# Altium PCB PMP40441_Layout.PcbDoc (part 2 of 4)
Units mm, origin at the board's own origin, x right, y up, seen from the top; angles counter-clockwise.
Board outline 66.04 x 61.04 mm, 4 copper layers (Top Layer, Layer 2, Layer 3, Bottom Layer), stack 2.028 mm thick; 208 components, 122 nets, 788 pads, 545 vias.
Unrouted connection lines stored in the file: 24.
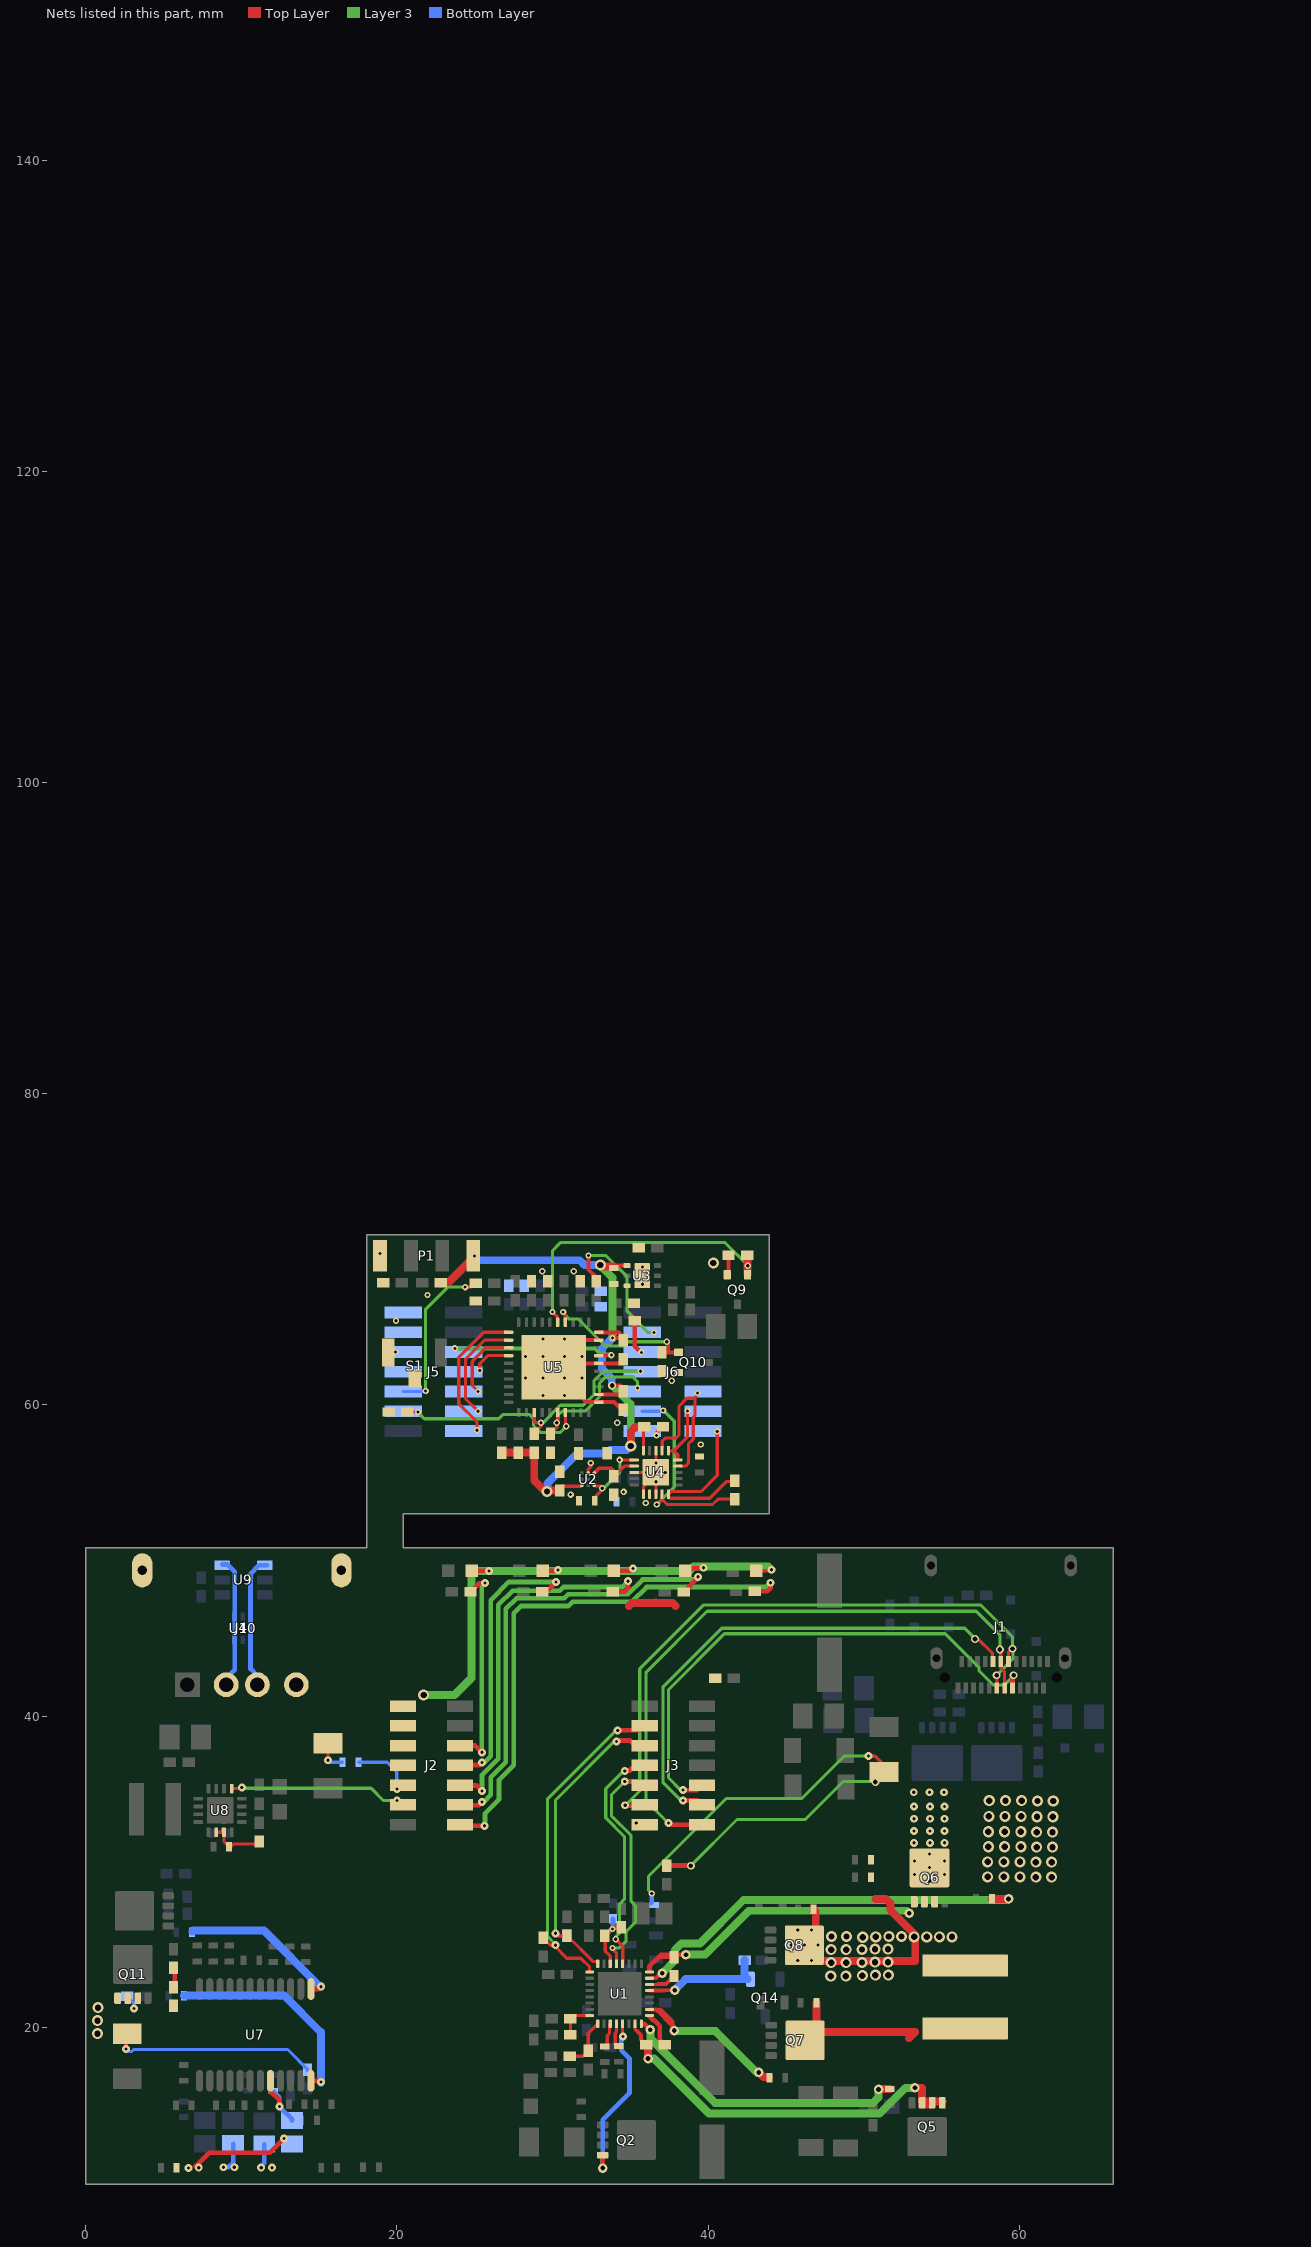
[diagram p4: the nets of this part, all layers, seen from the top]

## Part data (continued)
C115: "CAP, CERM, 1000 pF, 50 V, +/- 10%, X5R, 0402", Cap_Case=0402, Manufacturer=MuRata, Supplier Part Number 1=GRM155R61H102KA01D-ND, TempCo=X5R, Tolerance_%=10, Value1=Unknown, Value2=50V, ValueDisplayed=1000pF
C120 C136: "CAP, Polymer Hybrid, 56 µF, 25 V, +/- 20%, 50 ohm, 6.3x5.8 SMD", Manufacturer=Panasonic, Supplier Part Number 1=P15440CT-ND, Tolerance_%=20, Value1="50 ohm", Value2=25V, ValueDisplayed=56µF
C121 C122: "CAP, CERM, 47 µF, 25 V, +/- 20%, X5R, 1206_190", Cap_Case=1206, Manufacturer=TDK, Supplier Part Number 1=445-8047-1-ND, TempCo=X5R, Tolerance_%=20, Value1=Unknown, Value2=25V, ValueDisplayed=47µF
C125: "CAP, CERM, 1 µF, 25 V, +/- 10%, X5R, 0402", Cap_Case=0402, Manufacturer=MuRata, Supplier Part Number 1=490-10017-1-ND, TempCo=X5R, Tolerance_%=10, Value1=Unknown, Value2=25V, ValueDisplayed=1µF
C130 C131: "CAP, CERM, 330 pF, 50 V, +/- 5%, C0G/NP0, 0402", Cap_Case=0402, Manufacturer=MuRata, Supplier Part Number 1=490-1295-1-ND, TempCo=C0G/NP0, Tolerance_%=5, Value1=Unknown, Value2=50V, ValueDisplayed=330pF
C132 C135: "CAP, CERM, 22 µF, 35 V, +/- 20%, X5R, 1206_190", Cap_Case=1206, Manufacturer=TDK, Supplier Part Number 1=445-8045-1-ND, TempCo=X5R, Tolerance_%=20, Value1="0.002246 ohm", Value2=35V, ValueDisplayed=22µF
C137: "CAP, CERM, 1 µF, 16 V, +/- 10%, X5R, 0402", Cap_Case=0402, Manufacturer=TDK, Supplier Part Number 1=445-4978-1-ND, TempCo=X5R, Tolerance_%=10, Value1=Unknown, Value2=16V, ValueDisplayed=1µF
C140: "CAP, CERM, 33 pF, 50 V, +/- 5%, C0G/NP0, 0402", Cap_Case=0402, Manufacturer=MuRata, Supplier Part Number 1=81-GRM1555C1H330JA1D, TempCo=C0G/NP0, Tolerance_%=5, Value1=Unknown, Value2=50V, ValueDisplayed=33pF
C142: "CAP, CERM, 15 pF, 50 V, +/- 5%, C0G/NP0, 0402", Cap_Case=0402, Manufacturer=MuRata, Supplier Part Number 1=81-GRM1555C1H150JA1D, TempCo=C0G/NP0, Tolerance_%=5, Value1=Unknown, Value2=50V, ValueDisplayed=15pF
C143: "CAP, CERM, 1800 pF, 50 V, +/- 10%, X7R, 0402", Cap_Case=0402, Manufacturer=MuRata, Supplier Part Number 1=490-3246-1-ND, TempCo=X7R, Tolerance_%=10, Value1=Unknown, Value2=50V, ValueDisplayed=1800pF
C144: "CAP, CERM, 680 pF, 50 V, +/- 5%, C0G/NP0, 0402", Cap_Case=0402, Manufacturer=MuRata, Supplier Part Number 1=490-3240-1-ND, TempCo=C0G/NP0, Tolerance_%=5, Value1=Unknown, Value2=50V, ValueDisplayed=680pF
C151: "CAP, CERM, 2.2 µF, 16 V, +/- 10%, X5R, 0402", Cap_Case=0402, Manufacturer=TDK, Supplier Part Number 1=445-9085-1-ND, TempCo=X5R, Tolerance_%=10, Value1=Unknown, Value2=16V, ValueDisplayed=2.2µF
D1: "Diode, TVS, Uni, 24 V, 49 Vc, SOD-323", Manufacturer=Bourns, Supplier Part Number 1=CDSOD323-T24S-ND, Value1=W
D2 D3 D5: "Diode, Schottky, 45 V, 0.75 A, SOD-523", Manufacturer="Infineon Technologies", Supplier Part Number 1="BAS 52-02V H6327CT-ND", Value1=0.75A, Value2=0.6V
D4 D6: library part CMP-0005844-2, "Diode, Zener, 15 V, 300 mW, SOD-323", Manufacturer="NXP Semiconductor", Power_W=300mW, Supplier Part Number 1=568-6280-1-ND, Value1=0.3W
D7 D8: library part CMP-0082069-1, "Diode, Switching, 75 V, 0.15 A, SOD-323", Manufacturer="Micro Commercial Components", Supplier Part Number 1=1N4148WXTPMSCT-ND, Value1=0.15A, Value2=1V
D9: "Diode, Schottky, 30 V, 0.2 A, AEC-Q101, SOD-523", Manufacturer="ON Semiconductor", Supplier Part Number 1=RB521S30T1GOSCT-ND, Value1=0.2A, Value2=0.5V
D12 D13 D14 D15: "LED, Green, SMD", Color=green, Manufacturer=Lite-On, Power_TotalModule=0.1, Supplier Part Number 1=160-1183-1-ND, Value1=0.1W, Value2=2.1V
D16: "LED, Orange, SMD", Color=orange, Manufacturer=Lite-On, Power_TotalModule=0.075, Supplier Part Number 1=160-1434-1-ND, Value1=0.075W, Value2=2V
J1: "Receptacle, 0.5mm, USB TYPE C, R/A, SMT", Color=Black, Current_A=5, Manufacturer="Amphenol Canada", Supplier Part Number 1=12401610E4#2ACT-ND
J2 J3: "Receptacle, 1.27mm, 7x2, Gold, SMT", Manufacturer=Samtec, Supplier Part Number 1=SAM1226-07-ND
J4: "Connector, Receptacle, USB Type A, R/A, Bottom Mount TH", Manufacturer="Wurth Elektronik"
J5 J6: "Header, 1.27 mm, 7x2, Au, SMT", Manufacturer=FCI, Supplier Part Number 1=609-3730-ND
L5: "Inductor, Shielded, Composite, 2.2 µH, 3.7 A, 0.02 ohm, SMD", Manufacturer=Coilcraft, Supplier Part Number 1=994-XFL4020-222MEB, Value1="0.02 ohm", Value2=3.7A, ValueDisplayed=2.2µH
L8: "Inductor, Shielded, 2.2 µH, 16 A, 0.0067 ohm, AEC-Q200 Grade 1, SMD", Manufacturer=Coilcraft, Value1="0.0067 ohm", Value2=16A, ValueDisplayed=2.2µH
Logo5: library part Pb-Free
NT1: "Single point connection between nets."
P1: "Header, 2mm, 4x1, Gold, Black, R/A, SMT", Manufacturer=Harwin, Supplier Part Number 1=M22-5330405-ND
Q1 Q11: "MOSFET, N-CH, 25 V, 60 A, DQG0008A (VSON-CLIP-8)", Alternate Manufacturer=None, Manufacturer="Texas Instruments", Supplier Part Number 1=296-24522-1-ND, Value1="0.0044 ohm", Value2="6.2 nC"
Q2: "MOSFET, P-CH, -20 V, -60 A, VSON-CLIP-8", Alternate Manufacturer=None, Manufacturer="Texas Instruments", Value1="0.0065 ohm", Value2="10.8 nC"
Q3 Q4: library part CMP-0081533-1, "MOSFET, P-CH, -30 V, -35 A, PowerPAK 1212", Alternate Manufacturer=None, Manufacturer=Vishay-Siliconix, Supplier Part Number 1=SI7101DN-T1-GE3CT-ND, Value1="0.013 ohm", Value2="68 nC"
Q5 Q6 Q7 Q8: "MOSFET, N-CH, 30 V, 47 A, DQG0008A (VSON-CLIP-8)", Alternate Manufacturer=None, Manufacturer="Texas Instruments", Supplier Part Number 1=296-27210-1-ND, Value1="0.0094 ohm", Value2="3.9 nC"
Q9 Q10: "MOSFET, N-CH, 50 V, 0.21 A, SOT-323", Alternate Manufacturer=None, Manufacturer="Fairchild Semiconductor", Supplier Part Number 1=BSS138WCT-ND, Value1="6 ohm", Value2="1.1 nC"
Q14: library part CMP-0081321-1, "Transistor, NPN, 12 V, 2 A, SOT-23", Manufacturer="ON Semiconductor", Supplier Part Number 1=NSS12201LT1GOSCT-ND, Value1="2 A", Value2=330
R1 R2 R47 R53: "RES, 33, 5%, 0.125 W, 0805", Manufacturer=Vishay-Dale, Power_W=0.125, Supplier Part Number 1=541-33ACT-ND, TempCo="200 ppm/C", Tolerance_%=5, Value1=5%, Value2=0.125W, Value_Code=33R0, ValueDisplayed=33
R3 R6: "RES, 4.99, 1%, 0.063 W, 0402", Manufacturer=Vishay-Dale, Power_W=0.063, Supplier Part Number 1=541-4.99LLCT-ND, TempCo="100 ppm/C", Tolerance_%=1, Value1=1%, Value2=0.063W, Value_Code=4R99, ValueDisplayed=4.99
R4: "RES, 10 M, 5%, 0.063 W, 0402", Manufacturer=Vishay-Dale, Power_W=0.063, Supplier Part Number 1=541-10MJCT-ND, TempCo="200 ppm/C", Tolerance_%=5, Value1=5%, Value2=0.063W, Value_Code=10M0, ValueDisplayed=10M
R5: "RES, 3.0 M, 5%, 0.063 W, 0402", Manufacturer=Vishay-Dale, Power_W=0.063, Supplier Part Number 1=541-3.0MJCT-ND, TempCo="200 ppm/C", Tolerance_%=5, Value1=5%, Value2=0.063W, Value_Code=3M00, ValueDisplayed=3.0M
R7: "RES, 1.00 k, 1%, 0.125 W, 0805", Manufacturer=Vishay-Dale, Power_W=0.125, Supplier Part Number 1=541-1.00KCCT-ND, TempCo="100 ppm/C", Tolerance_%=1, Value1=1%, Value2=0.125W, Value_Code=1k00, ValueDisplayed=1.00k
R8: "RES, 1.0, 5%, 0.063 W, 0402", Manufacturer=Vishay-Dale, Power_W=0.063, Supplier Part Number 1=541-1.0JCT-ND, TempCo="200 ppm/C", Tolerance_%=5, Value1=5%, Value2=0.063W, Value_Code=1R00, ValueDisplayed=1.0
R9 R119: library part CMP-0026727-1, "RES, 1.00 M, 1%, 0.063 W, 0402", Manufacturer="Yageo America", Power_W=63mW, Supplier Part Number 1=311-1.00MLRCT-ND, TempCo="100 ppm/C", Tolerance_%=1%, Value2=0.063W, Value_Code=1M00, ValueDisplayed=1.00M
R10 R11 R12 R13 R16 R19 R34 R35 R76 R77 R81 R113: "RES, 0, 5%, 0.063 W, 0402", Manufacturer=Vishay-Dale, Power_W=0.063, Supplier Part Number 1=541-0.0JCT-ND, TempCo="200 ppm/C", Tolerance_%=5, Value1=5%, Value2=0.063W, Value_Code=0000, ValueDisplayed=0
R14 R32 R36 R87: "RES, 10.0 k, 1%, 0.063 W, 0402", Manufacturer=Vishay-Dale, Power_W=0.063, Supplier Part Number 1=541-10.0KLCT-ND, TempCo="100 ppm/C", Tolerance_%=1, Value1=1%, Value2=0.063W, Value_Code=10k0, ValueDisplayed=10.0k
R15: "RES, 470 k, 5%, 0.063 W, 0402", Manufacturer=Vishay-Dale, Power_W=0.063, Supplier Part Number 1=541-470KJCT-ND, TempCo="200 ppm/C", Tolerance_%=5, Value1=5%, Value2=0.063W, Value_Code=470k
R17: "RES, 196 k, 1%, 0.063 W, 0402", Manufacturer=Vishay-Dale, Power_W=0.063, Supplier Part Number 1=541-196KLCT-ND, TempCo="100 ppm/C", Tolerance_%=1, Value1=1%, Value2=0.063W, Value_Code=196k
R18: "RES, 1.0 M, 5%, 0.063 W, 0402", Manufacturer=Vishay-Dale, Power_W=0.063, Supplier Part Number 1=541-1.0MJCT-ND, TempCo="200 ppm/C", Tolerance_%=5, Value1=5%, Value2=0.063W, Value_Code=1M00, ValueDisplayed=1.0M
R20 R41 R42 R95: "RES, 100 k, 1%, 0.063 W, 0402", Manufacturer=Vishay-Dale, Power_W=0.063, Supplier Part Number 1=541-100KLCT-ND, TempCo="100 ppm/C", Tolerance_%=1, Value1=1%, Value2=0.063W, Value_Code=100k
R21: "RES, 200, 1%, 0.063 W, 0402", Manufacturer=Vishay-Dale, Power_W=0.063, Supplier Part Number 1=541-200LCT-ND, TempCo="100 ppm/C", Tolerance_%=1, Value1=1%, Value2=0.063W, Value_Code=200R, ValueDisplayed=200
R22 R122: library part CMP-0026815-1, "RES, 100 k, 0.1%, 0.063 W, 0402", Manufacturer="Susumu Co Ltd", Power_W=63mW, Supplier Part Number 1=RG10P100KBCT-ND, TempCo="25 ppm/C", Tolerance_%=0.1%, Value2=0.063W, Value_Code=100k
R23 R28 R128: "RES, 3.01 M, 1%, 0.063 W, 0402", Manufacturer=Vishay-Dale, Power_W=0.063, Supplier Part Number 1=541-3.01MLCT-ND, TempCo="100 ppm/C", Tolerance_%=1, Value1=1%, Value2=0.063W, Value_Code=3M01, ValueDisplayed=3.01M
R24: "RES, 2.00 M, 1%, 0.063 W, 0402", Manufacturer=Vishay-Dale, Power_W=0.063, Supplier Part Number 1=541-2.00MLCT-ND, TempCo="100 ppm/C", Tolerance_%=1, Value1=1%, Value2=0.063W, Value_Code=2M00, ValueDisplayed=2.00M
R25: library part CRCW0402100kJNED, "RES, 100 k, 5%, 0.063 W, 0402", Manufacturer=Vishay-Dale, Power_W=0.063, Supplier Part Number 1=541-100KJCT-ND, TempCo="200 ppm/C", Tolerance_%=5, Value1=5%, Value2=0.063W, Value_Code=100k
R26 R27: "RES, 100, 1%, 0.063 W, 0402", Manufacturer="Yageo America", Power_W=0.063, Supplier Part Number 1=311-100LRCT-ND, TempCo="100 ppm/C", Tolerance_%=1, Value1=1%, Value2=0.063W, Value_Code=100R, ValueDisplayed=100
R29: "RES, 1.00 M, 1%, 0.063 W, 0402", Manufacturer=Vishay-Dale, Power_W=0.063, Supplier Part Number 1=541-1.00MLCT-ND, TempCo="100 ppm/C", Tolerance_%=1, Value1=1%, Value2=0.063W, Value_Code=1M00, ValueDisplayed=1.00M
R30 R130: library part CMP-0026731-1, "RES, 330 k, 1%, 0.0625 W, 0402", Manufacturer="Yageo America", Power_W=62.5mW, Supplier Part Number 1=311-330KLRCT-ND, TempCo="100 ppm/C", Tolerance_%=1%, Value2=0.0625W, Value_Code=330k
R31: "RES, 200 k, 1%, 0.063 W, 0402", Manufacturer=Vishay-Dale, Power_W=0.063, Supplier Part Number 1=541-200KLCT-ND, TempCo="100 ppm/C", Tolerance_%=1, Value1=1%, Value2=0.063W, Value_Code=200k
R33: "RES, 220, 5%, 0.063 W, 0402", Manufacturer=Vishay-Dale, Power_W=0.063, Supplier Part Number 1=541-220JCT-ND, TempCo="200 ppm/C", Tolerance_%=5, Value1=5%, Value2=0.063W, Value_Code=220R, ValueDisplayed=220
R37: "RES, 100 k, 5%, 0.063 W, 0402", Manufacturer=Vishay-Dale, Power_W=0.063, Supplier Part Number 1=541-100KJCT-ND, TempCo="200 ppm/C", Tolerance_%=5, Value1=5%, Value2=0.063W, Value_Code=100k
R38: "RES, 47 k, 5%, 0.063 W, 0402", Manufacturer=Vishay-Dale, Power_W=0.063, Supplier Part Number 1=541-47KJCT-ND, TempCo="200 ppm/C", Tolerance_%=5, Value1=5%, Value2=0.063W, Value_Code=47k0, ValueDisplayed=47k
R45: "RES, 1.0 k, 5%, 0.063 W, 0402", Manufacturer=Vishay-Dale, Power_W=0.063, Supplier Part Number 1=541-1.0KJCT-ND, TempCo="200 ppm/C", Tolerance_%=5, Value1=5%, Value2=0.063W, Value_Code=1k00, ValueDisplayed=1.0k
R55 R57: "RES, 5.1 k, 5%, 0.063 W, 0402", Manufacturer=Vishay-Dale, Power_W=0.063, Supplier Part Number 1=541-5.1KJCT-ND, TempCo="200 ppm/C", Tolerance_%=5, Value1=5%, Value2=0.063W, Value_Code=5k10, ValueDisplayed=5.1k
R59: "Thermistor NTC, 10k ohm, 3%, 0402", Manufacturer=Panasonic, Power_W=0.066, Supplier Part Number 1=P12009CT-ND, Tolerance_%=3
R60 R72 R73: "RES, 0.01, 1%, 1 W, 1206", Manufacturer=Vishay-Dale, Power_W=1, Supplier Part Number 1=WSLP-.01CT-ND, TempCo="75 ppm/C", Value1=1%, Value2=1W, Value_Code=R010, ValueDisplayed=0.01
R62 R63: "RES, 100, 1%, 0.063 W, 0402", Manufacturer=Vishay-Dale, Power_W=0.063, Supplier Part Number 1=541-100LCT-ND, TempCo="100 ppm/C", Tolerance_%=1, Value1=1%, Value2=0.063W, Value_Code=100R, ValueDisplayed=100
R78 R79 R84: "RES, 10, 5%, 0.063 W, 0402", Manufacturer=Vishay-Dale, Power_W=0.063, Supplier Part Number 1=541-10JCT-ND, TempCo="200 ppm/C", Tolerance_%=5, Value1=5%, Value2=0.063W, Value_Code=10R0, ValueDisplayed=10
R82 R83: "RES, 56, 5%, 0.1 W, 0603", Manufacturer=Vishay-Dale, Power_W=0.1, Supplier Part Number 1=541-56GCT-ND, TempCo="200 ppm/C", Tolerance_%=5, Value1=5%, Value2=0.1W, Value_Code=56R0, ValueDisplayed=56
R86: "RES, 40.2 k, 1%, 0.063 W, 0402", Manufacturer=Vishay-Dale, Power_W=0.063, Supplier Part Number 1=541-40.2KLCT-ND, TempCo="100 ppm/C", Tolerance_%=1, Value1=1%, Value2=0.063W, Value_Code=40k2, ValueDisplayed=40.2k
R92: "RES, 383 k, 1%, 0.063 W, 0402", Manufacturer=Vishay-Dale, Power_W=0.063, Supplier Part Number 1=541-383KLCT-ND, TempCo="100 ppm/C", Tolerance_%=1, Value1=1%, Value2=0.063W, Value_Code=383k
R93: "RES, 80.6 k, 1%, 0.063 W, 0402", Manufacturer=Vishay-Dale, Power_W=0.063, Supplier Part Number 1=541-80.6KLCT-ND, TempCo="100 ppm/C", Tolerance_%=1, Value1=1%, Value2=0.063W, Value_Code=80k6, ValueDisplayed=80.6k
R94: "RES, 221 k, 1%, 0.063 W, 0402", Manufacturer=Vishay-Dale, Power_W=0.063, Supplier Part Number 1=541-221KLCT-ND, TempCo="100 ppm/C", Tolerance_%=1, Value1=1%, Value2=0.063W, Value_Code=221k
R98: "RES, 137 k, 1%, 0.063 W, 0402", Manufacturer=Vishay-Dale, Power_W=0.063, Supplier Part Number 1=541-137KLCT-ND, TempCo="100 ppm/C", Tolerance_%=1, Value1=1%, Value2=0.063W, Value_Code=137k
R99: "RES, 30.1 k, 1%, 0.063 W, 0402", Manufacturer=Vishay-Dale, Power_W=0.063, Supplier Part Number 1=541-30.1KLCT-ND, TempCo="100 ppm/C", Tolerance_%=1, Value1=1%, Value2=0.063W, Value_Code=30k1, ValueDisplayed=30.1k
R100 R101 R102 R103 R104: "RES, 3.3 k, 5%, 0.063 W, 0402", Manufacturer=Vishay-Dale, Power_W=0.063, Supplier Part Number 1=541-3.3KJCT-ND, TempCo="200 ppm/C", Tolerance_%=5, Value1=5%, Value2=0.063W, Value_Code=3k30, ValueDisplayed=3.3k
R105: "RES, 665 k, 1%, 0.063 W, 0402", Manufacturer=Vishay-Dale, Power_W=0.063, Supplier Part Number 1=541-665KLCT-ND, TempCo="100 ppm/C", Tolerance_%=1, Value1=1%, Value2=0.063W, Value_Code=665k
R106: "RES, 130 k, 1%, 0.063 W, 0402", Manufacturer=Vishay-Dale, Power_W=0.063, Supplier Part Number 1=541-130KLCT-ND, TempCo="100 ppm/C", Tolerance_%=1, Value1=1%, Value2=0.063W, Value_Code=130k
R112: "RES, 0.05, 1%, 1 W, 1206", Manufacturer=Panasonic, Power_W=1, Supplier Part Number 1=P0.05BVCT-ND, TempCo="50 ppm/C", Value1=1%, Value2=1W, Value_Code=R050, ValueDisplayed=0.05
S1: "Switch, SPST-NO, Off-Mom, 12 V, SMD", CurrentRating_mA=50, Manufacturer="Omron Electronic Components", Supplier Part Number 1=SW1021CT-ND
U1: library part CMP-0079371-1, "I2C Narrow VDC Buck-Boost Battery Charge Controller With System Power Monitor and Processor Hot Monitor, RSN0032B (WQFN-32)", Alternate Manufacturer="Texas Instruments", Alternate PartNumber=BQ25713RSNT
U2: library part CMP-0081747-1, "USB PD TCPCi Port Controller, YFP0009-C01 (DSBGA-9)", Alternate Manufacturer="Texas Instruments", Alternate PartNumber=TUSB422IYFPT, Operating Temprature Range="-40 to 85 C", Rating=Catalog
U3: "150-mA, 30-V, Ultra-Low IQ, Wide Input Low-Dropout Regulator with Reverse Current Protection, DRV0006A (WSON-6)", Alternate Manufacturer="Texas Instruments", Alternate PartNumber=TPS70933DRVT
U4: "USB Type C Interface Protector: Short-to-VBUS Over Voltage and IEC 61000-4-2 ESD Protection, RUK0020B", Alternate Manufacturer="Texas Instruments"
U5: "MSP430FR5949 16 MHz Ultra-Low-Power Microcontroller featuring 64 KB FRAM, 2 KB SRAM, 33 IO, RHA0040B (VQFN-40)", Alternate Manufacturer="Texas Instruments", Alternate PartNumber=MSP430FR5949IRHAT
U7: library part CMP-0077526-4, "3-5S Ultra Low-Power Voltage, Current, Temperature, and Open Wire Stackable Lithium-ion Battery Protector with Smart Cell Balancing, PW0024A (TSSOP-24)", Alternate Manufacturer="Texas Instruments"
U8: "4-17V 3A Step-Down Converter with DCS-Control, RGT0016C", Alternate Manufacturer="Texas Instruments", Alternate PartNumber=TLV62130RGTT
U9: "USB Dedicated Charging Port Controller, DBV0006A", Alternate Manufacturer="Texas Instruments", Alternate PartNumber=TPS2514ADBVT
U10: "DUAL CHANNEL HIGH SPEED ESD PROTECTION DEVICE, DRL0006A", Alternate Manufacturer="Texas Instruments"
ZZ1 ZZ5: library part AssemblyNoteLabel
ZZ2 ZZ3 ZZ4 ZZ6 ZZ7 ZZ8: library part AssemblyNote

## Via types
v1: diameter 0.711, hole 0.406, Top Layer to Bottom Layer, 205 vias
v2: diameter 0.508, hole 0.203, Top Layer to Bottom Layer, 152 vias
v3: diameter 0.406, hole 0.203, Top Layer to Bottom Layer, 67 vias
v4: diameter 0.5, hole 0.2, Top Layer to Bottom Layer, 66 vias
v5: diameter 0.508, hole 0.305, Top Layer to Bottom Layer, 16 vias
v6: diameter 0.61, hole 0.305, Top Layer to Bottom Layer, 16 vias
v7: diameter 0.403, hole 0.203, Top Layer to Bottom Layer, 9 vias
v8: diameter 0.5, hole 0.2, Top Layer to Bottom Layer, tented both sides, 6 vias
v9: diameter 0.5, hole 0.2, Top Layer to Bottom Layer, tented top, 5 vias
v10: diameter 0.914, hole 0.711, Top Layer to Bottom Layer, 2 vias
v11: diameter 0.229, hole 0.152, Top Layer to Bottom Layer, 1 vias

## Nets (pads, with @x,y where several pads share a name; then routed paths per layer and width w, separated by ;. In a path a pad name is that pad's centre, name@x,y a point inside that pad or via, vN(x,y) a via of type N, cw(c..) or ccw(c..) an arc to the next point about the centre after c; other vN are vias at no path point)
3V3: C7.2 C20.1 C22.2 C25.2 C26.2 P1.1 R25.2 R29.1 R31.1 R32.1 R36.1 R38.2 U2.A3 U3.1 U4.10 U5.32 U5.40 | length 48.6
  Top Layer w0.203: C7.2@30.48,54.762 31.833,54.762 U2.A3@31.89,54.82 ; C22.2@35.839,58.572 35.839,57.774 35.838,57.772 35.838,57.393 35.845,57.386 U4.10@35.845,57.059
  Top Layer w0.254: U5.32@32.978,60.662 34.373,60.662 C26.2@34.569,60.858 ; U5.40@32.978,64.662 34.245,64.662 ; v5(33.833,61.239) 34.366,61.239 34.544,61.062 C26.2@34.544,60.874 ; v3(33.858,64.287) C25.2@34.442,64.287 ; C20.1@33.975,68.951 U3.1@34.798,68.951 ; 34.29,64.643 34.544,64.389 C25.2@34.544,64.186 ; C25.2@34.544,64.141 C25.2@34.544,64.186 ; C25.2@34.62,64.16 C25.2@34.595,64.135 ; C25.2@34.773,64.135 C25.2@34.595,64.135 ; C25.2@34.544,64.186 C25.2@34.595,64.135
  Top Layer w0.508: R38.2@22.809,67.793 22.911,67.894 23.343,67.894 P1.1@25.006,69.558 ; R31.1@26.746,56.931 R29.1@28.794,56.931 ; R29.1@28.829,56.931 28.829,55.143 v1@29.616,54.356 ; v1@29.718,54.432 29.778,54.493 C7.2@30.455,54.493 ; v1@33.198,68.885 C20.1@33.934,68.885 ; v1(35.027,57.353) 35.027,58.268 35.331,58.572 C22.2@35.839,58.572
  Layer 3 w0.508: v1@33.071,68.961 33.858,68.174 v3(33.858,64.287) ; v5(33.833,61.239) 35.027,60.046 v1(35.027,57.353)
  Bottom Layer w0.254: R36.1@33.496,56.89 R36.1@33.528,56.89
  Bottom Layer w0.508: v3(24.994,69.571) 25.273,69.291 31.751,69.291 32.056,68.986 v1(33.071,68.986) ; v1@29.667,54.407 29.667,54.94 31.598,56.871 33.477,56.871 33.496,56.89 33.706,57.099 34.773,57.099 v1(35.027,57.353) ; v5@33.807,61.239 33.807,61.697 33.172,62.332 33.172,63.602 v3(33.858,64.287)
  other v1: 29.642,54.432
A_D+: J4.3 U9.1 U10.3 U10.4 | length 8.7
  Bottom Layer w0.305: 10.566,43.053 10.592,43.028 ; J4.3@11.074,41.986 11.024,42.037 11.024,42.596 10.592,43.028 ; U9.1@11.659,49.682 11.125,49.682 10.592,49.149 10.592,43.028
A_D-: J4.2 U9.6 U10.1 U10.6 | length 8.9
  Bottom Layer w0.305: U9.6@8.788,49.733 9.119,49.733 9.584,49.268 U10.1@9.584,46.394 ; J4.2@9.017,41.935 J4.2@9.071,41.989 ; J4.2@9.017,41.986 9.017,42.393 J4.2@9.024,42.399 ; J4.2@9.024,42.037 J4.2@9.024,42.399 ; U10.6@9.576,44.894 U10.1@9.576,46.394 ; U10.6@9.584,44.894 9.584,42.959 J4.2@9.024,42.399
AGND: C7.1 C16.2 C18.1 C19.1 C20.2 C21.1 C22.1 C23.2 C24.2 C25.1 C26.1 C27.2 C28.1 C29.2 C30.2 C31.2 C32.2 C33.1 C108.1 D12.2 D13.2 D14.2 D15.2 D16.2 J2.7 J2.9 J2.11 J2.13 J3.14 J5.7 J5.9 J5.11 J5.13 J6.14 P1.4 Q9.2 Q10.2 R19.2 R20.2 R23.2 R30.1 R37.1 R41.1 R42.1 R130.1 S1.2 S1.3 U2.C2 U3.3 U3.7@35.773,68.301 U4.8 U4.13 U4.16 U4.17 U4.18 U4.21@36.645,55.659 U5.31 U5.36 U5.39 U5.41@30.078,62.412 | length 53.1
  Top Layer w0.203: U2.C2@32.29,55.62 32.29,55.849 32.461,56.021 v3(32.461,56.261) ; U4.13@35.245,55.659 U4.21@36.035,55.659 ; U4.16@35.845,54.259 35.845,54.742 U4.21@35.966,54.864 ; U4.18@36.645,54.259 v4(36.645,55.059) U4.21@36.645,55.161 ; U4.8@36.645,57.059 v4(36.645,56.259) 36.645,56.218 U4.21@36.652,56.21 ; D16.2@43.092,49.34 44.005,49.34 v2(44.069,49.403)
  Top Layer w0.254: U5.41@31.242,62.662 U5.36@32.978,62.662 ; U5.41@31.269,64.162 U5.39@32.978,64.162 ; U5.41@31.598,60.757 32.182,60.173 33.96,60.173 34.458,59.674 C26.1@34.544,59.674 ; U5.36@32.969,62.662 34.214,62.662 34.493,62.941 C25.1@34.544,62.941 ; v3@36.678,57.988 v3(36.678,58.039) 36.678,58.176 C22.1@37.1,58.598 ; Q9.2@41.199,68.402 41.31,68.513 R41.1@41.31,69.621
  Top Layer w0.305: D12.2@24.804,49.34 25.895,49.34 v2(25.908,49.327) ; D13.2@29.376,49.34 30.315,49.34 v2(30.353,49.378) ; D14.2@33.948,49.34 35.039,49.34 v2(35.179,49.479) ; D15.2@38.52,49.34 38.774,49.34 38.935,49.501 39.11,49.501 39.113,49.505 39.576,49.505 39.625,49.455 v2(39.7,49.53)
  Top Layer w0.508: 34.913,47.079 35.103,47.269 36.594,47.269 36.619,47.295 36.652,47.262 37.721,47.262 37.916,47.066
  Layer 3 w0.508: v1(21.717,41.351) 23.698,41.351 24.79,42.443 24.79,49.022 25.095,49.327 v2(25.908,49.327) 38.792,49.327 39.071,49.606 43.866,49.606 v2(44.069,49.403)
  other v1: 40.335,69.113
  other v2: 35.382,33.122
  other v3: 35.992,53.696 31.166,54.229 34.569,54.407 39.522,57.455 34.163,58.852 37.668,61.544 19.914,63.398 19.939,65.405 21.971,67.056 29.337,68.58 31.369,68.58 18.923,69.723
  other v4: 36.045,55.659 36.045,55.659 36.645,55.659 37.245,55.659 37.245,55.659 29.393,60.587 30.763,60.587 28.253,61.727 29.393,61.727 30.763,61.727 31.903,61.727 28.253,63.097 29.393,63.097 30.763,63.097 31.903,63.097 29.393,64.237 30.763,64.237 35.773,67.751 35.773,68.851
BATDRVB: Q2.4 U1.21 | length 11.2
  Top Layer w0.203: U1.21@34.508,20.224 34.508,19.536 34.536,19.507 v2(34.536,19.406)
  Top Layer w0.305: Q2.4@33.222,11.776 33.177,11.73 33.223,11.684 v6(33.223,10.947)
  Bottom Layer w0.305: v6(33.223,10.947) 33.223,14.046 34.95,15.773 34.95,17.983 34.417,18.517 34.417,19.205 34.544,19.332 v2@34.544,19.406 ; v2@34.519,19.406 v2@34.519,19.431
C_CC1: J1.A5 J3.9 J6.9 U4.4 U4.7 | length 44.6
  Top Layer w0.203: U4.7@37.052,57.28 37.052,57.677 37.236,57.861 37.922,57.861 38.125,58.064 38.125,59.919 38.633,60.427 39.141,60.427 ; U4.4@38.125,56.058 38.557,56.058 38.735,56.236 38.735,57.485 39.04,57.79 39.04,59.207 39.167,59.334 39.167,60.477 v3@39.319,60.63
  Top Layer w0.305: v2@38.379,35.23 39.282,35.23 J3.9@39.612,35.56 ; J1.A5@59.559,41.81 59.559,42.49 v5@59.665,42.596
  Layer 3 w0.203: v2@38.405,35.23 38.252,35.23 37.465,36.017 37.465,41.707 41.046,45.288 54.661,45.288 54.665,45.284 55.249,45.284 57.4,43.133 57.4,42.93 58.344,41.986 59.03,41.986 v5@59.639,42.596
  other v2: 38.379,35.255
  other v3: 39.319,60.757
  other v5: 59.639,42.621
C_CC2: J1.B5 J3.11 J6.11 U4.5 U4.6 | length 37.2
  Top Layer w0.203: U4.6@37.465,57.023 37.77,57.023 37.795,57.048 ; U4.5@38.045,56.459 38.045,56.799 37.795,57.048 ; v3(38.684,59.614) 38.684,57.937 37.795,57.048 ; v5(57.15,44.958) 57.252,44.958 57.302,45.009 58.242,44.069 58.242,44.062 58.268,44.036 58.268,43.552 J1.B5@58.309,43.51
  Top Layer w0.305: v2(38.379,34.569) 39.333,34.569 J3.11@39.612,34.29
  Layer 3 w0.203: v2@38.354,34.544 38.278,34.544 37.109,35.712 37.109,41.885 40.869,45.644 55.345,45.644 55.35,45.639 56.494,45.639 v5@57.175,44.958
C_D+: J1.A6 J1.B6 J3.13 J6.13 R21.2 U4.20 | length 52.2
  Top Layer w0.203: U4.20@37.445,54.259 37.445,54.097 37.541,54 40.107,54 41.173,55.067 R21.2@41.732,55.067 ; U4.20@37.49,54.28 37.643,54.432 39.548,54.432 40.589,55.474 v3(40.589,58.293) ; J1.B6@58.801,43.459 58.801,43.086 59.059,42.828 J1.A6@59.059,41.81 ; J1.B6@58.809,43.51 v5@58.809,44.163
  Top Layer w0.305: v2(37.465,33.122) 37.567,33.02 J3.13@39.612,33.02
  Layer 3 w0.203: v2@37.465,33.096 36.017,34.544 36.017,42.824 39.929,46.736 57.226,46.736 58.75,45.212 58.75,44.348 v5@58.699,44.298
  other v5: 58.75,44.272
C_D-: J1.A7 J1.B7 J3.12 J6.12 R21.1 U4.19 | length 55.5
  Top Layer w0.203: v3@36.728,53.569 37.045,53.885 37.045,53.913 ; U4.19@37.045,54.259 37.045,53.913 ; R21.1@41.631,53.95 40.64,53.95 40.284,53.594 37.363,53.594 37.045,53.913 ; v5@58.547,42.647 58.559,42.635 J1.A7@58.559,41.81 ; J1.B7@59.309,43.51 59.309,44.094 v5@59.538,44.323
  Top Layer w0.305: v2@34.671,34.239 35.876,34.239 J3.12@35.927,34.29
  Layer 3 w0.203: v2@34.696,34.265 35.611,35.179 35.611,43.028 39.726,47.142 57.506,47.142 59.563,45.085 v5(59.563,44.323) v5@59.563,44.298 ; v3(36.703,53.594) 37.821,54.712 37.821,58.953 v3@37.122,59.652 ; v5(58.547,42.621) 59.588,43.663 v5@59.588,44.298
  Bottom Layer w0.203: J6.12@35.769,59.588 37.084,59.588 v3@37.135,59.639
  other v2: 34.671,34.265
  other v3: 37.109,59.639
CC1: C19.2 U2.C1 U4.12 | length 3.4
  Top Layer w0.203: C19.2@33.985,55.397 33.985,55.423 34.621,56.059 U4.12@35.245,56.059
  Top Layer w0.254: U2.C1@32.69,55.62 32.995,55.924 33.763,55.924 33.96,55.728 C19.2@33.96,55.321
CC2: C18.2 U2.A1 U4.11 | length 5.5
  Top Layer w0.203: C18.2@32.715,53.823 32.715,54.051 33.198,54.534 v3(33.198,54.635) ; v3@33.122,54.559 33.122,54.686 33.02,54.788 ; v3@33.223,54.635 33.071,54.788 33.02,54.788 ; v3@34.336,56.459 U4.11@35.245,56.459 ; 32.983,54.788 32.722,54.788 U2.A1@32.69,54.82 32.69,54.788 32.983,54.788 ; 32.983,54.788 33.02,54.788
  Layer 3 w0.203: v3(33.198,54.635) 33.299,54.635 34.341,55.677 v3@34.341,56.464
  other v3: 34.315,56.464
CELL1: R53.2 | length 1.6
  Bottom Layer w0.305: 9.169,10.998 9.474,11.303 R53.2@9.474,12.509
  other v2: 8.865,10.998 9.55,10.998
CELL2: R47.2 | length 1.3
  Bottom Layer w0.305: 11.405,11.201 11.481,11.278 R47.2@11.481,12.483
  other v2: 11.278,10.973 11.963,10.973
CELL_N: R2.2 R35.1 | length 6.7
  Top Layer w0.254: v2@7.061,11.074 7.163,10.973 v2(7.264,10.973)
  Top Layer w0.305: v2@7.061,11.074 7.925,11.938 11.836,11.938 v2(12.751,12.852)
  other v2: 6.604,10.947
CHG_ACN: C114.1 C115.1 Q6.5 Q6.6 Q6.7 Q6.8 Q6.9@54.229,30.241 R3.1 R8.1 R72.2 | length 36.3
  Top Layer w0.203: v5@38.887,30.353 v5(38.887,30.378) ; v2(50.317,37.44) 50.343,37.414 50.749,37.414 51.308,36.855 R72.2@51.562,36.855
  Top Layer w0.305: R8.1@37.342,30.389 38.851,30.389 v5@38.887,30.353
  Layer 3 w0.203: v7(36.373,28.6) 36.17,28.804 36.17,29.693 41.173,34.696 46.025,34.696 48.768,37.44 v2(50.317,37.44) ; v5(38.887,30.378) 41.859,33.35 46.253,33.35 48.692,35.789 v5@50.698,35.789
  Bottom Layer w0.305: R3.1@36.347,27.991 36.373,28.016 v7(36.373,28.6)
  other v1: 61.062,29.642 62.078,29.642 57.963,29.667 59.004,29.667 60.046,29.667 61.062,30.607 62.078,30.607 57.963,30.632 59.004,30.632 60.046,30.632 61.112,31.572 62.128,31.572 58.014,31.598 59.055,31.598 60.096,31.598 61.112,32.537 62.128,32.537 58.014,32.563 59.055,32.563 60.096,32.563 61.138,33.528 62.154,33.528 58.039,33.553 59.08,33.553 60.122,33.553 61.166,34.537 62.182,34.537 58.067,34.562 59.109,34.562 60.15,34.562
  other v2: 53.238,31.852 54.254,31.852 55.194,31.852 53.238,32.614 54.254,32.614 55.194,32.614 53.238,33.401 54.254,33.401 55.194,33.401 53.238,34.188 54.254,34.188 55.194,34.188 53.213,35.103 54.229,35.103 55.169,35.103
  other v4: 54.229,29.379 53.254,29.817 55.204,29.817 54.229,30.255 53.254,30.693 55.204,30.693
  other v5: 50.749,35.763
  other v8: 54.229,31.131
CHG_OK: J3.8 J6.8 R29.2 U1.4 U5.23 | length 25.4
  Top Layer w0.203: U5.23@28.828,59.512 28.828,58.955 28.931,58.852 v3(29.261,58.852) 29.261,58.623 R29.2@28.829,58.191 ; v7@34.061,25.654 34.519,25.197 34.519,24.085 U1.4@34.508,24.074
  Top Layer w0.305: v2@34.671,36.5 34.976,36.5 35.306,36.83 J3.8@35.927,36.83 J3.8@35.876,36.779
  Layer 3 w0.203: v3@29.286,58.826 29.362,58.826 30.505,59.969 31.979,59.969 32.664,60.655 32.664,61.544 33.274,62.154 v3(35.662,62.154) ; v7(34.067,25.651) 34.067,25.812 34.315,26.06 34.315,27.915 34.62,28.219 34.62,32.258 33.426,33.452 33.426,35.331 34.544,36.449 v2@34.595,36.449
  other v2: 34.646,36.474
CHG_SRN: R79.1 U1.19 | length 1.6
  Top Layer w0.203: R79.1@33.52,18.66 33.52,19.462 33.663,19.605 33.663,20.18 U1.19@33.708,20.224
CHG_SRP: R78.1 U1.20 | length 1.4
  Top Layer w0.203: R78.1@34.028,18.837 34.028,19.616 34.108,19.696 U1.20@34.108,20.224
COMP1: C140.1 R86.2 U1.16 | length 2.4
  Top Layer w0.203: C140.1@31.148,19.507 R86.2@31.148,20.549 31.349,20.749 U1.16@32.383,20.749
COMP2: C142.2 C144.2 U1.17 | length 3.3
  Top Layer w0.203: C142.2@31.098,18.136 31.955,18.136 C144.2@32.301,18.482 32.301,19.618 U1.17@32.908,20.224
DSGBUS: Q9.1 R41.2 U5.5 | length 19.4
  Top Layer w0.203: v3(29.997,65.964) 30.328,65.634 U5.5@30.328,65.312
  Top Layer w0.508: Q9.1@42.535,68.362 42.535,69.636 R41.2@42.545,69.647
  Layer 3 w0.203: v3(29.997,65.964) 29.997,69.912 30.468,70.383 30.48,70.383 30.531,70.434 41.072,70.434 v3@42.57,68.936
  other v3: 42.545,68.936
EN_A: J2.3 J5.3 R20.1 U5.27 U8.13 | length 23.3
  Top Layer w0.203: U8.13@9.386,35.334 9.96,35.334 v2(10.033,35.408) ; R20.1@20.676,59.538 21.336,59.538 v3@21.361,59.512 ; v3@30.828,58.657 U5.27@30.828,59.512
  Layer 3 w0.203: v2(10.033,35.408) 10.084,35.357 18.339,35.357 19.126,34.569 v2(20.015,34.569) ; v3@21.361,59.512 21.768,59.106 26.557,59.106 26.836,59.385 28.51,59.385 28.778,59.117 28.778,58.674 29.235,58.217 30.48,58.217 v3(30.886,58.623)
  other v3: 21.361,59.538
EN_BUS: Q10.1 R42.2 U5.4 | length 9.9
  Top Layer w0.203: v3@30.81,65.811 30.81,65.33 U5.4@30.828,65.312
  Top Layer w0.254: R42.2@37.033,63.373 37.44,63.373 ; v3@37.44,64.008 37.44,63.373 ; Q10.1@38.1,63.373 37.44,63.373
  Layer 3 w0.203: v3(30.683,65.964) 30.683,65.901 31.078,65.507 31.674,65.507 33.401,63.779 34.569,63.779 34.798,64.008 34.849,64.059 v3(37.338,64.059)
EN_OTG: J3.10 J6.10 R37.2 U1.5 U5.26 | length 24.4
  Top Layer w0.203: R37.2@29.87,58.141 30.277,58.547 v3(30.277,58.852) 30.328,58.852 U5.26@30.328,59.512 ; v7@33.833,25.07 34.108,24.795 U1.5@34.108,24.074
  Top Layer w0.305: v2(34.646,35.789) 35.699,35.789 J3.10@35.927,35.56
  Layer 3 w0.203: v3@30.251,58.801 30.35,58.9 30.35,59.312 30.653,59.614 32.126,59.614 33.02,60.508 33.02,61.392 33.426,61.798 35.154,61.798 35.458,61.493 v3(35.458,61.087) ; v7(33.85,25.095) 34.29,25.095 34.722,25.527 34.722,25.713 34.716,25.72 34.716,26.097 34.722,26.103 34.722,26.137 35.33,26.745 35.33,27.811 35.052,28.089 35.052,32.334 35.047,32.334 33.782,33.599 33.782,34.925 v2@34.62,35.763 ; v2@34.62,35.839 v2@34.658,35.801
GCHG: R57.2 U7.13 | length 10.6
  Top Layer w0.305: U7.13@14.472,22.457 14.964,22.457 v2(15.113,22.606)
  Bottom Layer w0.305: R57.2@6.833,26.213 R57.2@6.883,26.213 ; v2(15.113,22.606) v2@15.113,22.631
  Bottom Layer w0.508: R57.2@6.858,26.162 R57.2@6.909,26.213 ; R57.2@6.883,26.213 R57.2@6.909,26.213 ; v2(15.113,22.606) 15.062,22.606 11.455,26.213 R57.2@6.909,26.213
GDSG: R55.1 U7.12 | length 13.6
  Top Layer w0.305: U7.12@14.472,16.557 v2@15.066,16.557
  Bottom Layer w0.508: R55.1@6.325,22.022 6.325,22.047 12.751,22.047 15.113,19.685 v2(15.113,16.485) v2@15.113,16.459
GND_A: J4.4 J4.5 J4.6 R112.2 R113.2 | length 2.1
  Top Layer w0.203: v2@15.57,37.186 R112.2@15.57,38.255
  Bottom Layer w0.203: v2@15.545,37.135 15.646,37.033 R113.2@16.51,37.033
  other v2: 15.57,37.16
GND_BK: C106.1 NT1.1 R106.1 U8.6 U8.7 | length 3.6
  Top Layer w0.203: U8.6@8.386,32.534 U8.7@8.886,32.534 8.886,31.932 9.144,31.674 R106.1@9.312,31.674 ; R106.1@9.312,31.598 9.49,31.775 10.989,31.775 C106.1@11.151,31.937
HB_HDV1: R76.1 U1.31 | length 26.6
  Top Layer w0.254: U1.31@36.233,23.149 36.624,23.149 36.624,23.17 36.657,23.17 36.957,23.47 v6@37.033,23.47 ; v6@37.051,23.394 v6(37.051,23.47)
  Top Layer w0.508: R76.1@58.242,28.245 v6@59.182,28.245
  Layer 3 w0.508: v6(37.051,23.47) 37.864,24.283 37.864,24.958 38.28,25.375 39.472,25.375 42.266,28.169 59.233,28.169 v6(59.309,28.245)
HB_HDV2: R77.2 U1.24 | length 19
  Top Layer w0.305: U1.24@35.739,20.224 35.902,20.224 v6(36.289,19.838)
  Top Layer w0.508: v6@50.952,16.027 R77.2@51.689,16.027
  Layer 3 w0.508: v6@36.297,19.812 36.297,19.279 40.437,15.138 50.597,15.138 50.952,15.494 v6(50.952,16.002) v6@50.952,16.027
HB_HVDD1: C138.2 U1.30 | length 1.8
  Top Layer w0.203: U1.30@36.233,22.749 36.813,22.749
  Top Layer w0.254: 36.813,22.764 37.046,22.764 37.066,22.784 37.305,22.784 C138.2@37.813,23.292
HB_HVDD2: C139.1 U1.25 | length 2.3
  Top Layer w0.305: U1.25@36.233,20.697 36.482,20.448 36.541,20.448 36.898,20.09 36.898,19.193 C139.1@37.219,18.873
HB_LDV2: R81.2 U1.26 | length 11
  Top Layer w0.254: U1.26@36.233,21.149 36.253,21.129 36.682,21.129 37.686,20.125
  Top Layer w0.305: 36.754,21.082 36.957,21.082 37.686,20.353 37.686,20.125 37.821,19.99 v6(37.821,19.787)
  Top Layer w0.508: v6(43.256,17.094) 43.561,16.789 R81.2@43.917,16.789
  Layer 3 w0.508: v6@37.846,19.761 40.462,19.761 43.129,17.094 v6(43.256,17.094)
HB_LG1: D5.1 Q14.1 U1.29 | length 7.9
  Top Layer w0.254: U1.29@36.233,22.349 37.206,22.349 37.235,22.378 v6(37.864,22.378)
  Bottom Layer w0.508: v6@37.846,22.377 38.557,23.089 42.547,23.089 42.351,23.285 D5.1@42.351,24.308
HB_SW1: C130.1 C138.1 L8.1 Q6.1 Q6.2 Q6.3 Q8.5 Q8.6 Q8.7 Q8.8 Q8.9@46.185,25.275 U1.32 | length 33.9
  Top Layer w0.254: U1.32@36.233,23.576 U1.32@36.233,23.602
  Top Layer w0.305: U1.32@36.233,23.602 36.233,23.922 36.975,24.664 37.025,24.613 37.076,24.664 v6(38.575,24.664) ; 36.875,24.532 C138.1@37.754,24.532
  Top Layer w0.508: Q8.9@46.28,24.256 53.315,24.256 53.315,25.929 51.709,27.534 51.709,27.951 51.415,28.245 50.765,28.245 ; C130.1@46.787,27.584 46.92,27.452 Q8.8@46.92,26.25 ; Q8.9@46.838,24.638 Q8.5@47.22,24.256
  Layer 3 w0.508: v6(38.575,24.664) 39.802,24.664 42.621,27.483 52.756,27.483 v6@52.934,27.305
  other v1: 47.883,23.286 48.848,23.286 49.911,23.317 50.749,23.343 51.587,23.343 47.908,24.15 48.874,24.15 49.886,24.155 50.724,24.181 51.562,24.181 47.908,24.988 48.874,24.988 49.886,24.994 50.724,25.019 51.562,25.019 49.936,25.781 50.775,25.806 53.238,25.806 54.051,25.806 54.864,25.806 55.677,25.806 47.934,25.826 48.899,25.826 51.613,25.832 52.426,25.832
  other v4: 45.761,24.3 46.637,24.3 45.323,25.275 46.199,25.275 45.761,26.25 46.637,26.25
  other v6: 52.934,27.33
  other v8: 47.075,25.275
HB_SW2: C131.1 C139.2 L8.2 Q5.1 Q5.2 Q5.3 Q7.5 Q7.6 Q7.7 Q7.8 Q7.9@46.235,19.154 U1.23 | length 34.2
  Top Layer w0.203: U1.23@35.308,20.224 35.308,19.856 35.379,19.784
  Top Layer w0.254: 35.425,19.754 35.679,19.5 35.679,19.213 C139.2@36.017,18.875
  Top Layer w0.508: C139.2@36.017,18.898 36.017,18.875 36.144,18.748 v6(36.144,17.983) ; Q7.9@46.238,19.686 53.315,19.686 52.918,19.289 ; Q7.9@46.97,20.129 C131.1@46.97,21.553 ; v6(53.289,16.104) 53.746,16.104 53.758,16.092 53.758,15.239 Q5.1@55.052,15.239 ; Q5.3@53.797,15.037 54.299,15.037 Q5.2@54.402,15.139
  Layer 3 w0.508: v6(36.144,17.983) 36.525,17.983 40.056,14.453 51.029,14.453 52.68,16.104 v6(53.289,16.104)
IBAT: C153.1 J3.4 J6.4 R27.1 U1.9 | length 31.4
  Top Layer w0.203: C153.1@29.405,25.746 29.878,25.273 v2(30.193,25.273) 30.193,25.162 30.92,24.435 31.822,24.435 32.383,23.874 U1.9@32.383,23.549
  Top Layer w0.254: v3(32.309,69.596) 32.309,68.682 32.817,68.174 R27.1@32.817,67.935
  Top Layer w0.305: v2(34.188,39.065) 34.214,39.091 35.648,39.091 J3.4@35.927,39.37
  Layer 3 w0.203: v2(30.193,25.273) 30.193,25.317 29.685,25.825 29.685,34.689 33.96,38.964 34.112,38.964 v2@34.214,39.065 ; v3@32.334,69.596 33.426,69.596 34.798,68.224 34.798,66.015 36.17,64.643 v3(36.525,64.643) ; v2(34.188,39.065) v2@34.214,39.091
IO_A: J2.5 J5.5 R33.2 R113.1 | length 14.3
  Top Layer w0.203: v3(24.384,67.564) 24.765,67.564 R33.2@25.019,67.818
  Layer 3 w0.203: v3(21.844,60.884) 21.844,66.142 23.266,67.564 v3(24.384,67.564)
  Bottom Layer w0.203: R113.1@17.526,37.033 19.38,37.033 19.99,36.424 v2@19.99,35.357 ; J5.5@20.402,60.858 v3@21.793,60.858
  other v2: 20.015,35.306
IPORT: C152.1 J3.6 J6.6 R26.1 R98.1 U1.8 | length 22.6
  Top Layer w0.203: v2(30.193,26.035) 30.193,25.959 30.259,25.892 R98.1@30.929,25.892 32.589,24.233 32.816,24.233 32.908,24.141 U1.8@32.908,24.074
  Top Layer w0.305: v2(34.112,38.354) 34.188,38.43 34.976,38.43 35.306,38.1 J3.6@35.927,38.1 ; R26.1@35.281,65.405 35.281,63.779 v3@35.712,63.348
  Layer 3 w0.203: v2(30.193,26.035) 30.193,34.587 33.909,38.303 34.087,38.303 v2@34.112,38.329
  Bottom Layer w0.203: v2@30.201,26.035 30.353,25.883 C152.1@30.912,25.883
  other v3: 35.712,63.373
LED0: J2.2 J5.2 R104.2 U5.11 | length 43.9
  Top Layer w0.203: v3(25.146,58.369) 25.146,58.903 23.978,60.071 23.978,63.068 25.572,64.662 U5.11@27.178,64.662
  Top Layer w0.254: v3@25.146,58.344 v3(25.146,58.369)
  Top Layer w0.305: J2.2@24.054,33.071 24.181,32.944 v2(25.629,32.944) ; R104.2@42.993,48.019 43.802,48.019 43.942,48.158 44.018,48.235 v2(44.018,48.565)
  Layer 3 w0.305: v2@25.654,32.918 25.654,33.731 26.568,34.646 26.568,35.89 27.508,36.83 27.508,46.609 27.965,47.066 31.013,47.066 31.293,47.346 35.103,47.346 36.043,48.285 43.713,48.285 43.739,48.311 43.815,48.387 43.967,48.539 43.993,48.565 v2(44.018,48.565)
LED1: J2.4 J5.4 R103.2 U5.12 | length 36.3
  Top Layer w0.203: v3(25.222,59.588) 24.409,60.401 24.409,62.941 25.63,64.162 U5.12@27.178,64.162
  Top Layer w0.254: v3@25.209,59.576 v3@25.222,59.563
  Top Layer w0.305: J2.4@23.927,34.265 25.273,34.265 v2(25.476,34.468) ; R103.2@38.421,47.968 39.345,48.892 v2(39.345,48.946)
  Layer 3 w0.305: v2(25.476,34.468) 25.578,34.468 26.035,34.925 26.035,36.068 27,37.033 27,46.888 27.686,47.574 30.759,47.574 31.013,47.828 34.849,47.828 35.789,48.768 39.218,48.768 v2@39.37,48.92
LED2: J2.6 J5.6 R102.2 U5.13 | length 29.2
  Top Layer w0.203: v3(25.222,60.858) 24.841,61.239 24.841,62.789 25.715,63.662 U5.13@27.178,63.662
  Top Layer w0.305: J2.6@24.13,35.535 25.121,35.535 v2(25.476,35.179) ; R102.2@33.874,47.993 34.633,47.993 34.849,48.209 v2(34.849,48.666)
  Layer 3 w0.305: v2(25.476,35.179) 25.476,36.22 25.705,36.449 25.708,36.449 25.809,36.551 25.818,36.551 26.492,37.225 26.492,37.236 26.518,37.262 26.518,47.142 27.432,48.057 30.457,48.057 30.686,48.285 34.468,48.285 v2(34.849,48.666) v2@34.874,48.692
LED3: J2.8 J5.8 R101.2 U5.14 | length 20.7
  Top Layer w0.203: v3(25.324,62.205) 25.324,62.636 25.85,63.162 U5.14@27.178,63.162 ; R101.2@29.327,47.993 R101.2@29.604,47.993
  Top Layer w0.305: J2.8@24.003,36.855 25.324,36.855 v2(25.476,37.008) ; R101.2@29.604,47.993 v2(30.226,48.616)
  Layer 3 w0.305: v2(25.476,37.008) 25.629,37.008 26.035,37.414 26.035,47.447 27.203,48.616 v2@30.251,48.616
LED4: J2.10 J5.10 R100.2 U5.37 | length 24.9
  Top Layer w0.254: U5.37@32.978,63.162 33.774,63.162 v3@33.807,63.195
  Top Layer w0.305: J2.10@24.068,38.1 25.019,38.1 v2@25.476,37.643 ; R100.2@24.73,47.993 25.276,48.539 v2(25.654,48.539)
  Layer 3 w0.254: v3(23.724,63.627) v3@23.875,63.627 ; v3@23.876,63.627 32.715,63.627 33.121,63.221 33.731,63.221 v3@33.782,63.17
  Layer 3 w0.305: v2(25.476,37.668) 25.527,37.668 25.451,37.744 25.451,48.362 v2@25.654,48.565
  other v3: 33.782,63.195
NetC1_2: C1.2 R2.1 U7.8 | length 4.3
  Top Layer w0.305: U7.8@11.887,16.535 11.862,16.51 11.862,15.9 12.471,15.291 v2@12.471,14.91
  Bottom Layer w0.305: C1.2@12.04,15.9 12.446,15.494 v2@12.446,14.91 ; v2@12.471,14.91 12.471,14.859 13.259,14.072 R2.1@13.259,13.997
  other v2: 12.459,14.903
NetC2_1: C2.1 R92.2 R94.1 U1.6 | length 3.6
  Top Layer w0.203: R94.1@33.393,25.612 33.393,24.892 33.708,24.578 U1.6@33.708,24.074
  Top Layer w0.305: R94.1@33.368,25.892 33.377,25.892 33.902,26.417 C2.1@34.417,26.417
  Bottom Layer w0.305: v7@33.833,26.289 33.884,26.34 R92.2@33.884,26.975
  other v7: 33.85,26.315
NetC3_1: C3.1 C4.2 | length 1.2
  Top Layer w0.305: C3.1@5.715,22.581 C4.2@5.715,23.809
NetC3_2: C3.2 Q11.1 Q11.2 Q11.3 R4.2 R60.2 R63.2 | length 14.4
  Top Layer w0.254: v2(2.591,18.593) 2.591,19.509 R60.2@2.667,19.586
  Bottom Layer w0.203: R4.2@2.616,21.971 2.667,21.971 3.099,21.539 v2(3.099,21.209) ; v2@2.642,18.593 2.794,18.44 2.952,18.44 3.079,18.567 12.974,18.567 13.101,18.44 13.106,18.44 14.249,17.297 R63.2@14.249,17.196
  Bottom Layer w0.254: v2(2.591,18.593) v2@2.642,18.593
  other v1: 0.762,19.583 0.762,20.422 0.787,21.26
